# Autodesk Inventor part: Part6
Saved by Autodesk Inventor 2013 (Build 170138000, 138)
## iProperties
Created: 2012-07
Part Number: Part6
Material: Generic
Document SubType Name: Modeling
Designer: Paul
Density: 1 g/cm^3
Author: Paul
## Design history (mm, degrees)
node "User Library-Arduino Mega.SAT1"
body "Solid1"
node "Base1"
